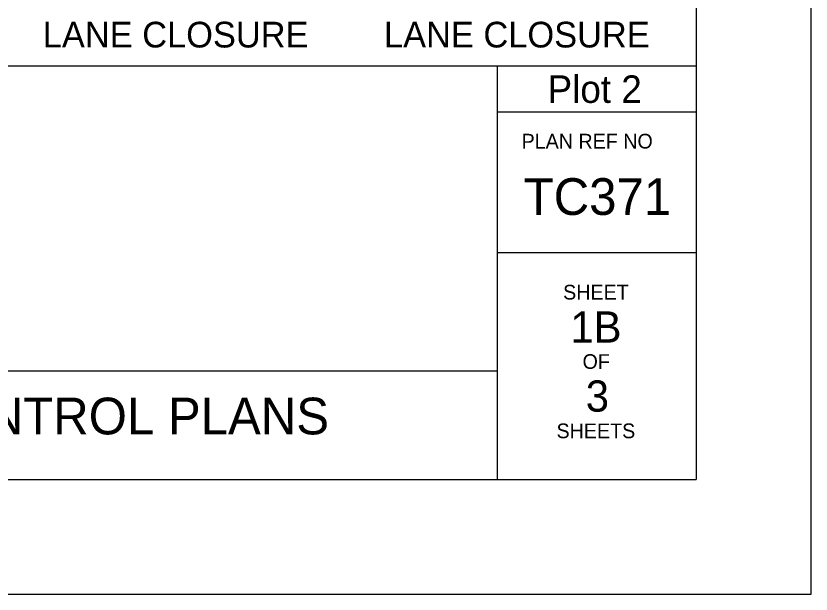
# Model space of a CAD drawing. Extents: x 99958 to 100136, y 99935 to 100013.
# Drawn here: x 100033.899 to 100036.062, y 99999.687 to 100001.262 of the extents above; entities that cross this region are included whole.
import ezdxf

# ---------------------------------------------------------------- set-up
doc = ezdxf.new("R2010")
doc.units = 0
for name, color, linetype in [('SH_GI_PlotLimits', 7, 'Continuous'), ('SH_GI_SheetBorder', 7, 'Continuous'), ('SH_GI_SheetLocationText', 7, 'Continuous'), ('SH_GI_SheetTextInCells', 7, 'Continuous'), ('SH_GI_TitleBlockText', 7, 'Continuous'), ('TR_SN_ConstructionSigns', 7, 'Continuous')]:
    doc.layers.add(name, color=color, linetype=linetype)

msp = doc.modelspace()

# ---------------------------------------------------------------- linework, layer by layer
at = {"layer": 'SH_GI_PlotLimits'}
msp.add_lwpolyline([(100019.0625, 99999.6875), (100036.0625, 99999.6875), (100036.0625, 100010.6875), (100019.0625, 100010.6875)], close=True, dxfattribs=at)
at = {"layer": 'SH_GI_SheetBorder'}
for p, q in [((100035.75, 100010.375), (100035.75, 100000)), ((100020, 100001.1259), (100035.75, 100001.1259)), ((100035.2079, 100001.1259), (100035.2079, 100000)), ((100035.2079, 100001.0008), (100035.75, 100001.0008)), ((100035.2079, 100000.6176), (100035.75, 100000.6176)), ((100032.2055, 100000.2955), (100035.2079, 100000.2955)), ((100020, 100000), (100035.75, 100000))]:
    msp.add_line(p, q, dxfattribs=at)

# ---------------------------------------------------------------- texts
msp.add_text('PLAN REF NO', height=0.040032, dxfattribs=at).set_placement((100035.2747, 100000.9008))
at = {"layer": 'SH_GI_SheetLocationText'}
msp.add_text('Plot 2', height=0.075, dxfattribs=at).set_placement((100035.3454, 100001.025))
at = {"layer": 'SH_GI_SheetTextInCells'}
for s, p in [('SHEET', (100035.3877, 100000.4896)), ('OF', (100035.4406, 100000.3008)), ('SHEETS', (100035.3698, 100000.112))]:
    msp.add_text(s, height=0.04003, dxfattribs=at).set_placement(p)
at = {"layer": 'SH_GI_TitleBlockText'}
for s, height, p in [('TC371', 0.1, (100035.2803, 100000.72)), ('1B', 0.085, (100035.4076, 100000.3723)), ('3', 0.085, (100035.4493, 100000.1843)), ('TYPICAL TRAFFIC CONTROL PLANS', 0.1, (100032.4251, 100000.1224))]:
    msp.add_text(s, height=height, dxfattribs=at).set_placement(p)
at = {"layer": 'TR_SN_ConstructionSigns'}
for p in [(100033.9718, 100001.1759), (100034.9003, 100001.1759)]:
    msp.add_text('LANE CLOSURE', height=0.07, rotation=360, dxfattribs=at).set_placement(p)

doc.saveas('drawing.dxf')
